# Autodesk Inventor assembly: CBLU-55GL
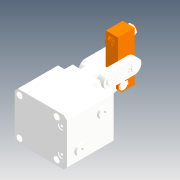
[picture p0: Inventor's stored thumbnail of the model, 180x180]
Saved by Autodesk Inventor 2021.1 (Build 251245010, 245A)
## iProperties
Created: 2019-05
Part Number: CBLU-55GL
Description: STEP AP214
Document SubType Name: Assembly
Designer: user
Title: CBLU-55GL.STEP
Revision Number: ÈÎºÎ
Sending System: SolidWorks 2016
Preprocessor: SwSTEP 2.0
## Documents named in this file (12)
- D:\Vault_2016\Projekty\Clamptek\Hydraulic\CBLU\CBLU-55\Inventor\CBLU-55GL\CBLU-55GL.iam
- D:\Vault_2016\Projekty\Clamptek\Hydraulic\CBLU\CBLU-55\Inventor\CBLU-55GL\CBLU-55CL±¾Ìå_1_2.ipt
- D:\Vault_2016\Projekty\Clamptek\Hydraulic\CBLU\CBLU-55\Inventor\CBLU-55GL\changxiao.ipt
- D:\Vault_2016\Projekty\Clamptek\Hydraulic\CBLU\CBLU-55\Inventor\CBLU-55GL\duanxiao.ipt
- D:\Vault_2016\Projekty\Clamptek\Hydraulic\CBLU\CBLU-55\Inventor\CBLU-55GL\huosaigan_1_1.ipt
- D:\Vault_2016\Projekty\Clamptek\Hydraulic\CBLU\CBLU-55\Inventor\CBLU-55GL\kahuang.ipt
- D:\Vault_2016\Projekty\Clamptek\Hydraulic\CBLU\CBLU-55\Inventor\CBLU-55GL\kahuang01.ipt
- D:\Vault_2016\Projekty\Clamptek\Hydraulic\CBLU\CBLU-55\Inventor\CBLU-55GL\liangan.ipt
- D:\Vault_2016\Projekty\Clamptek\Hydraulic\CBLU\CBLU-55\Inventor\CBLU-55GL\luogan.ipt
- D:\Vault_2016\Projekty\Clamptek\Hydraulic\CBLU\CBLU-55\Inventor\CBLU-55GL\luomu.ipt
- D:\Vault_2016\Projekty\Clamptek\Hydraulic\CBLU\CBLU-55\Inventor\CBLU-55GL\yabi.ipt
- D:\Vault_2016\Projekty\Clamptek\Hydraulic\CBLU\CBLU-55\Inventor\CBLU-55GL\ÄÚÁù½Ç¶ÂÍ·×îÐÂ1-4_1.ipt
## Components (18 placed, 18 different names)
1. CBLU-55CL±¾Ìå_1_2_1
2. changxiao_2
3. duanxiao_3
4. huosaigan_1_1_4
5. kahuang_5
6. kahuang01_6
7. liangan_7
8. luogan_8
9. luomu_9
10. yabi_10
11. liangan_11
12. kahuang01_12
13. changxiao_13
14. kahuang_14
15. kahuang_15
16. kahuang_16
17. ÄÚÁù½Ç¶ÂÍ·×îÐÂ1-4_1_17
18. ÄÚÁù½Ç¶ÂÍ·×îÐÂ1-4_1_18
